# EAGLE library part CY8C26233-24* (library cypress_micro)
The CY8C25xxx/26xxx family of Programmable System-on-Chip (PSoC) microcontrollers offers a fast core, Flash program memory and SRAM data memory with configurable analog and digital peripheral blocks in a range of convinient pinouts and memory size on one single chip.
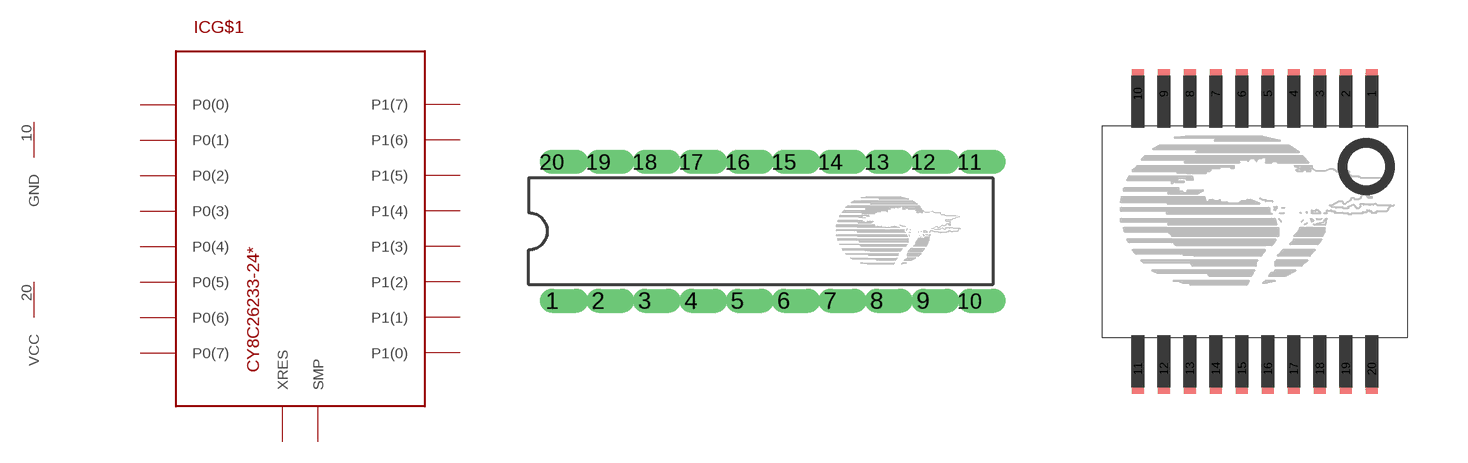
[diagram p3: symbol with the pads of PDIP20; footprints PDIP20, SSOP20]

Designator prefix IC; gates G$1=CY8C26233 G$2=GND G$3=VCC

## CY8C26233-24PI  [PDIP20]
1  G$1:P0(7)
2  G$1:P0(5)
3  G$1:P0(3)
4  G$1:P0(1)
5  G$1:SMP  out
6  G$1:P1(7)
7  G$1:P1(5)
8  G$1:P1(3)
9  G$1:P1(1)
10  G$2:GND  pwr
11  G$1:P1(0)
12  G$1:P1(2)
13  G$1:P1(4)
14  G$1:P1(6)
15  G$1:XRES  in
16  G$1:P0(0)
17  G$1:P0(2)
18  G$1:P0(4)
19  G$1:P0(6)
20  G$3:VCC  pwr

## CY8C26233-24PVI  [SSOP20]
Pads as for PDIP20

## CY8C26233-24SI  [SOIC20]
Pads as for PDIP20

## Footprint PDIP20 (pad centres in mm)
Plastic Dual Inline Package with 20 pins
drill 0.813 offset: 1 -11.43,-3.81; 2 -8.89,-3.81; 3 -6.35,-3.81; 4 -3.81,-3.81; 5 -1.27,-3.81; 6 1.27,-3.81; 7 3.81,-3.81; 8 6.35,-3.81; 9 8.89,-3.81; 10 11.43,-3.81; 11 11.43,3.81; 12 8.89,3.81; 13 6.35,3.81; 14 3.81,3.81; 15 1.27,3.81; 16 -1.27,3.81; 17 -3.81,3.81; 18 -6.35,3.81; 19 -8.89,3.81; 20 -11.43,3.81

## Footprint SSOP20 (pad centres in mm)
Shrunk Small Outline Package with 20 pins
smd 0.305 x 1.245: 1 2.924,3.441; 2 2.274,3.441; 3 1.624,3.441; 4 0.974,3.441; 5 0.325,3.44; 6 -0.326,3.441; 7 -0.976,3.441; 8 -1.626,3.441; 9 -2.276,3.441; 10 -2.926,3.441; 11 -2.924,-3.441; 12 -2.274,-3.441; 13 -1.624,-3.441; 14 -0.974,-3.441; 15 -0.324,-3.441; 16 0.326,-3.441; 17 0.976,-3.441; 18 1.626,-3.441; 19 2.276,-3.441; 20 2.926,-3.441

## Footprint SOIC20 (pad centres in mm)
SOIC with 20 pins
smd 0.6 x 2.2: 1 5.715,4.235; 2 4.445,4.235; 3 3.175,4.235; 4 1.905,4.235; 5 0.635,4.235; 6 -0.635,4.235; 7 -1.905,4.235; 8 -3.175,4.235; 9 -4.445,4.235; 10 -5.715,4.235; 11 -5.715,-4.235; 12 -4.445,-4.235; 13 -3.175,-4.235; 14 -1.905,-4.235; 15 -0.635,-4.235; 16 0.635,-4.235; 17 1.905,-4.235; 18 3.175,-4.235; 19 4.445,-4.235; 20 5.715,-4.235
